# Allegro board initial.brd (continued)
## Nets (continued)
GND: C1.1(A<0>) C2.1(A<0>) C3.1(A<0>) C4.2(B<0>) C5.1(A<0>) C6.1(A<0>) C7.1(A<0>) C8.1(A<0>) C9.1(A<0>) C10.1(A<0>) C11.1(A<0>) C12.1(A<0>) C13.1(A<0>) C14.1(A<0>) C15.1(A<0>) C16.1(A<0>) C17.1(A<0>) C18.1(A<0>) C19.1(A<0>) C20.1(A<0>) C21.1(A<0>) C24.1(A<0>) C25.1(A<0>) C26.1(A<0>) C27.1(A<0>) C28.1(A<0>) C29.1(A<0>) C30.1(A<0>) C31.1(A<0>) C32.1(A<0>) C33.1(A<0>) C34.1(A<0>) C35.1(A<0>) C40.1(A<0>) C41.1(A<0>) C42.1(A<0>) C43.1(A<0>) C44.1(A<0>) C45.1(A<0>) C46.1(A<0>) C47.1(A<0>) C48.1(A<0>) C49.1(A<0>) C50.1(A<0>) C51.1(A<0>) C52.1(A<0>) C53.1(A<0>) C54.1(A<0>) C55.1(A<0>) C56.1(A<0>) C57.1(A<0>) C58.1(A<0>) C61.1(A<0>) C62.1(A<0>) C63.1(A<0>) C64.1(A<0>) C65.1(A<0>) C66.1(A<0>) C67.1(A<0>) C68.1(A<0>) C69.1(A<0>) C70.1(A<0>) C75.1(A<0>) C76.1(A<0>) C77.1(A<0>) C78.1(A<0>) C79.1(A<0>) C80.1(A<0>) C81.1(A<0>) C83.1(A<0>) C84.1(A<0>) C85.1(A<0>) C86.1(A<0>) C87.1(A<0>) C88.1(A<0>) C89.1(A<0>) C90.1(A<0>) C91.1(A<0>) C92.1(A<0>) C93.1(A<0>) C94.1(A<0>) C95.1(A<0>) C96.1(A<0>) C97.1(A<0>) C98.1(A<0>) C99.1(A<0>) C100.1(A<0>) C101.1(A<0>) C106.1(A<0>) C107.1(A<0>) C108.1(A<0>) C109.1(A<0>) C110.1(A<0>) C111.1(A<0>) C112.1(A<0>) C113.1(A<0>) C114.1(A<0>) C115.1(A<0>) C120.1(A<0>) C121.1(A<0>) C122.1(A<0>) C123.1(A<0>) C124.1(A<0>) C125.1(A<0>) C126.1(A<0>) C127.1(A<0>) C128.1(A<0>) C129.1(A<0>) C134.1(A<0>) C135.1(A<0>) C136.1(A<0>) C137.1(A<0>) C138.1(A<0>) C139.1(A<0>) C140.1(A<0>) C141.1(A<0>) C142.1(A<0>) C143.1(A<0>) C148.1(A<0>) C149.1(A<0>) C150.1(A<0>) C151.1(A<0>) C152.1(A<0>) C153.1(A<0>) C154.1(A<0>) C155.1(A<0>) C156.1(A<0>) C157.1(A<0>) C162.1(A<0>) C163.1(A<0>) C164.1(A<0>) C165.1(A<0>) C166.1(A<0>) C167.1(A<0>) C168.1(A<0>) C169.1(A<0>) C170.1(A<0>) C171.1(A<0>) C176.1(A<0>) C177.1(A<0>) C178.1(A<0>) C179.1(A<0>) C180.1(A<0>) C181.1(A<0>) C182.1(A<0>) C183.1(A<0>) C184.1(A<0>) C185.1(A<0>) C186.1(A<0>) C187.1(A<0>) DS2.2(K1) DS3.2(K1) DS4.2(K1) LK5.1(A<0>) LK5.2(B<0>) LK6.1(A<0>) LK6.2(B<0>) LK7.1(A<0>) LK7.2(B<0>) LK8.1(A<0>) LK8.2(B<0>) LK9.1(A<0>) LK10.1(A<0>) PL1.1(A<0>) PL2.1(A<0>) PL3.1(A<0>) PL4.1(A<0>) PL5.1(A<0>) PL6.1(A<0>) PL7.1(A<0>) PL9.AB1(GND1) PL9.AB2(GND2) PL9.AB3(GND3) PL9.AB4(GND4) PL9.AB5(GND5) PL9.AB6(GND6) PL9.AB7(GND7) PL9.AB8(GND8) PL9.AB9(GND9) PL9.AB10(GND10) PL9.CD1(GND11) PL9.CD2(GND12) PL9.CD3(GND13) PL9.CD4(GND14) PL9.CD5(GND15) PL9.CD6(GND16) PL9.CD7(GND17) PL9.CD8(GND18) PL9.CD9(GND19) PL9.CD10(GND20) PL9.EF1(GND21) PL9.EF2(GND22) PL9.EF3(GND23) PL9.EF4(GND24) PL9.EF5(GND25) PL9.EF6(GND26) PL9.EF7(GND27) PL9.EF8(GND28) PL9.EF9(GND29) PL9.EF10(GND30) PL10.AB1(GND1) PL10.AB2(GND2) PL10.AB3(GND3) PL10.AB4(GND4) PL10.AB5(GND5) PL10.AB6(GND6) PL10.AB7(GND7) PL10.AB8(GND8) PL10.AB9(GND9) PL10.AB10(GND10) PL10.CD1(GND11) PL10.CD2(GND12) PL10.CD3(GND13) PL10.CD4(GND14) PL10.CD5(GND15) PL10.CD6(GND16) PL10.CD7(GND17) PL10.CD8(GND18) PL10.CD9(GND19) PL10.CD10(GND20) PL10.EF1(GND21) PL10.EF2(GND22) PL10.EF3(GND23) PL10.EF4(GND24) PL10.EF5(GND25) PL10.EF6(GND26) PL10.EF7(GND27) PL10.EF8(GND28) PL10.EF9(GND29) PL10.EF10(GND30) R1.1(A<0>) R2.1(A<0>) R7.1(A<0>) R9.1(A<0>) R11.1(A<0>) R13.1(A<0>) R15.1(A<0>) R17.1(A<0>) R19.1(A<0>) R28.1(A<0>) R69.1(A<0>) R71.1(A<0>) R73.1(A<0>) R75.1(A<0>) R77.1(A<0>) R79.1(A<0>) R81.1(A<0>) R90.1(A<0>) R91.1(A<0>) R109.1(A<0>) R122.1(A<0>) R124.1(A<0>) R136.1(A<0>) R137.1(A<0>) R144.1(A<0>) R155.1(A<0>) R157.1(A<0>) R159.1(A<0>) R167.1(A<0>) R172.1(A<0>) R188.1(A<0>) R190.1(A<0>) R203.1(A<0>) R208.1(A<0>) R224.1(A<0>) R226.1(A<0>) R239.1(A<0>) R244.1(A<0>) R260.1(A<0>) R262.1(A<0>) R270.1(A<0>) R271.1(A<0>) R272.1(A<0>) R275.1(A<0>) R310.1(A<0>) R312.1(A<0>) R313.1(A<0>) R315.1(A<0>) R317.1(A<0>) R318.1(A<0>) SK2.9(SHIELD1) SK2.10(SHIELD2) SK4.GND1 SK4.GND2 SK4.GND3 SK4.GND4 SK4.GND5 SK4.GND6 SK4.GND7 SK4.GND8 SK4.GND9 SK4.GND10 SK4.GND11 SW1.1(A<0>) SW1.2(A<1>) SW2.B SW2.D TP5.1(TEST<0>) TP19.1(TEST<0>) TP24.1(TEST<0>) U1.3 U2.1(GND) U3.9(GND1) U3.20(GND2) U4.5(GND) U5.4(GND) U5.5(2A) U5.6(2B) U6.5(GND) U7.1(GND) U8.4(GND) U9.1(GND) U10.4(GND) U11.3(GND) U12.1(GND1) U12.4(GND2) U12.6(ENA*) U12.11(ENB*) U12.15(GND3) U12.18(GND4) U12.22(ENC*) U12.27(END*) U12.29(GND5) U12.32(GND6) U13.1(GND) U14.6(GND1) U14.9(OE2) U14.10(GND2) U15.2(GND) U16.6(GND1) U16.8(OE0) U16.10(GND2) U17.1(GND1) U17.4(GND2) U17.6(ENA*) U17.11(ENB*) U17.15(GND3) U17.18(GND4) U17.22(ENC*) U17.27(END*) U17.29(GND5) U17.32(GND6) U18.1(GND) U19.1(GND) U20.1(GND) U21.1(GND) U22.1(GND) U23.1(GND) U24.1(GND) U25.1(GND) U26.1(GND) U27.1(GND) U28.1(GND) U29.1(GND) U30.3(GND) U31.3(GND) U32.8(VSS) U33.A19(EXTVCC) U33.D23(SGND) U33.G1(PGND1) U33.G23(FCB) U33.H7(PGND2) U33.H9(PGND3) U33.H11(PGND4) U33.H13(PGND5) U33.H15(PGND6) U33.H17(PGND7) U33.J1(PGND8) U33.K7(PGND9) U33.K9(PGND10) U33.K11(PGND11) U33.K13(PGND12) U33.K15(PGND13) U33.K17(PGND14) U33.L2(PGND15) U33.L4(PGND16) U33.L6(PGND17) U33.L8(PGND18) U33.L10(PGND19) U33.L12(PGND20) U33.L14(PGND21) U33.L16(PGND22) U33.L18(PGND23) U33.L20(PGND24) U33.L22(PGND25) U33.M2(PGND26) U33.M4(PGND27) U33.M6(PGND28) U33.M8(PGND29) U33.M10(PGND30) U33.M12(PGND31) U33.M14(PGND32) U33.M16(PGND33) U33.M18(PGND34) U33.M20(PGND35) U33.M22(PGND36) U33.N2(PGND37) U33.N4(PGND38) U33.N6(PGND39) U33.N8(PGND40) U33.N10(PGND41) U33.N12(PGND42) U33.N14(PGND43) U33.N16(PGND44) U33.N18(PGND45) U33.N20(PGND46) U33.N22(PGND47) U34.4(GND) U35.4(GND) U36.1(GND) U37.1(GND) U38.1(GND) U39.1(GND) U40.1(GND) U41.1(GND) U42.1(GND) U43.1(GND) U44.1(GND) U45.1(GND) U46.1(GND) U47.1(GND) U48.1(GND) U49.1(GND) U50.1(GND) U51.1(GND) U52.1(GND) U53.1(GND) U54.1(GND) U55.1(GND) U56.1(GND) U57.1(GND) U58.1(GND) U59.1(GND) U59.21(OE/DM2*) U60.1(GND) U60.21(OE/DM2*)
CLK_4_5_FPGA: PL9.E1(PAIR21_A) R31.2(B<0>) TP18.1(TEST<0>)
CLK_4_5_MAIN: R30.2(B<0>) U3.7(ICLK)
CLK_99: R3.2(B<0>) U3.8(FBIN) U10.2(DIN1) U10.3(DIN2)
CLK_99_S: PL9.E2(PAIR22_A) R5.2(B<0>) TP12.1(TEST<0>)
CLK_EC_RTM: TP13.1(TEST<0>) U4.7(ROUT1) U5.2(1B) U8.1(IN) U14.5(INB)
CLK_EC_RTM_N: PL9.B3(PAIR3_B) R273.1(A<0>) U4.1(RIN1*)
CLK_EC_RTM_P: PL9.A3(PAIR3_A) R273.2(B<0>) U4.2(RIN1)
CLK_LA_N: SK4.2LA U12.35(D3Z)
CLK_LA_P: SK4.1LA U12.36(D3Y)
CLK_LB_N: SK4.2LB U12.39(D1Z)
CLK_LB_P: SK4.1LB U12.40(D1Y)
CLK_LC_N: SK4.2LC U12.43(C3Z)
CLK_LC_P: SK4.1LC U12.44(C3Y)
CLK_LD_N: SK4.2LD U12.47(C1Z)
CLK_LD_P: SK4.1LD U12.48(C1Y)
CLK_LE_N: SK4.2LE U12.51(B3Z)
CLK_LE_P: SK4.1LE U12.52(B3Y)
CLK_LF_N: SK4.2LF U12.55(B1Z)
CLK_LF_P: SK4.1LF U12.56(B1Y)
CLK_LG_N: SK4.2LG U12.59(A3Z)
CLK_LG_P: SK4.1LG U12.60(A3Y)
CLK_LH_N: SK4.2LH U12.63(A1Z)
CLK_LH_P: SK4.1LH U12.64(A1Y)
CLK_UA_N: SK4.2UA TP16.1(TEST<0>) U12.33(D4Z)
CLK_UA_P: SK4.1UA TP15.1(TEST<0>) U12.34(D4Y)
CLK_UB_N: SK4.2UB U12.37(D2Z)
CLK_UB_P: SK4.1UB U12.38(D2Y)
CLK_UC_N: SK4.2UC U12.41(C4Z)
CLK_UC_P: SK4.1UC U12.42(C4Y)
CLK_UD_N: SK4.2UD U12.45(C2Z)
CLK_UD_P: SK4.1UD U12.46(C2Y)
CLK_UE_N: SK4.2UE U12.49(B4Z)
CLK_UE_P: SK4.1UE U12.50(B4Y)
CLK_UF_N: SK4.2UF U12.53(B2Z)
CLK_UF_P: SK4.1UF U12.54(B2Y)
CLK_UG_N: SK4.2UG U12.57(A4Z)
CLK_UG_P: SK4.1UG U12.58(A4Y)
CLK_UH_N: SK4.2UH U12.61(A2Z)
CLK_UH_P: SK4.1UH U12.62(A2Y)
DATA_LA_N: SK4.5LA U17.35(D3Z)
DATA_LA_P: SK4.4LA U17.36(D3Y)
DATA_LB_N: SK4.5LB U17.39(D1Z)
DATA_LB_P: SK4.4LB U17.40(D1Y)
DATA_LC_N: SK4.5LC U17.43(C3Z)
DATA_LC_P: SK4.4LC U17.44(C3Y)
DATA_LD_N: SK4.5LD U17.47(C1Z)
DATA_LD_P: SK4.4LD U17.48(C1Y)
DATA_LE_N: SK4.5LE U17.51(B3Z)
DATA_LE_P: SK4.4LE U17.52(B3Y)
DATA_LF_N: SK4.5LF U17.55(B1Z)
DATA_LF_P: SK4.4LF U17.56(B1Y)
DATA_LG_N: SK4.5LG U17.59(A3Z)
DATA_LG_P: SK4.4LG U17.60(A3Y)
DATA_LH_N: SK4.5LH U17.63(A1Z)
DATA_LH_P: SK4.4LH U17.64(A1Y)
DATA_UA_N: SK4.5UA TP22.1(TEST<0>) U17.33(D4Z)
DATA_UA_P: SK4.4UA TP21.1(TEST<0>) U17.34(D4Y)
DATA_UB_N: SK4.5UB U17.37(D2Z)
DATA_UB_P: SK4.4UB U17.38(D2Y)
DATA_UC_N: SK4.5UC U17.41(C4Z)
DATA_UC_P: SK4.4UC U17.42(C4Y)
DATA_UD_N: SK4.5UD U17.45(C2Z)
DATA_UD_P: SK4.4UD U17.46(C2Y)
DATA_UE_N: SK4.5UE U17.49(B4Z)
DATA_UE_P: SK4.4UE U17.50(B4Y)
DATA_UF_N: SK4.5UF U17.53(B2Z)
DATA_UF_P: SK4.4UF U17.54(B2Y)
DATA_UG_N: SK4.5UG U17.57(A4Z)
DATA_UG_P: SK4.4UG U17.58(A4Y)
DATA_UH_N: SK4.5UH U17.61(A2Z)
DATA_UH_P: SK4.4UH U17.62(A2Y)
DIV2: R1.2(B<0>) U3.3(DIV2)
DRIVE_ST: PL1.2(B<0>) U3.11(2XDRIVE)
ENABLE: R140.1(A<0>) U31.2(A) U32.5(P1)
ESD_SEGMENT_1: R274.2(B<0>)
ESD_SEGMENT_2: R275.2(B<0>)
ESD_SEGMENT_3: R274.1(A<0>)
FAILURE_LED: DS1.2(K1) R143.1(A<0>) U32.9(P4)
FAST_CLK_FPGA_N: PL9.D3(PAIR13_B) U13.7(OUT-)
FAST_CLK_FPGA_P: PL9.C3(PAIR13_A) U13.6(OUT+)
FAST_DATA_N: PL10.B3(PAIR3_B) R67.1(A<0>) U17.20(B)
FAST_DATA_P: PL10.A3(PAIR3_A) R67.2(B<0>) U17.19(A)
FPGA_F0: PL10.B7(PAIR7_B) U3.12(F0)
FPGA_F1: PL10.A8(PAIR8_A) U3.13(F1)
FPGA_F2: PL10.B8(PAIR8_B) U3.14(F2)
FPGA_F3: PL10.A9(PAIR9_A) U3.15(F3)
FPGA_F4: PL10.B9(PAIR9_B) U3.16(F4)
FPGA_F5: PL10.A10(PAIR10_A) U3.17(F5)
FPGA_F6: PL10.B10(PAIR10_B) U3.18(F6)
FPGA_R0: PL10.A4(PAIR4_A) U3.24(R0)
FPGA_R1: PL10.B4(PAIR4_B) U3.25(R1)
FPGA_R2: PL10.A5(PAIR5_A) U3.26(R2)
FPGA_R3: PL10.B5(PAIR5_B) U3.27(R3)
FPGA_R4: PL10.A6(PAIR6_A) U3.28(R4)
FPGA_R5: PL10.B6(PAIR6_B) U3.1(R5)
FPGA_R6: PL10.A7(PAIR7_A) U3.2(R6)
FPGA_SPARE_IN1_I_N: C34.2(B<0>) C36.1(A<0>) R82.2(B<0>) SK2.2
FPGA_SPARE_IN1_I_P: C32.2(B<0>) C37.1(A<0>) R82.1(A<0>) SK2.1
FPGA_SPARE_IN1_N: PL10.B2(PAIR2_B) R96.2(B<0>) U18.7(OUT-) U20.2(IN-)
FPGA_SPARE_IN1_P: PL10.A2(PAIR2_A) R96.1(A<0>) U18.6(OUT+) U20.3(IN+)
FPGA_SPARE_IN2_I_N: C35.2(B<0>) C38.1(A<0>) R83.2(B<0>) SK2.5
FPGA_SPARE_IN2_I_P: C33.2(B<0>) C39.1(A<0>) R83.1(A<0>) SK2.4
FPGA_SPARE_IN2_N: PL9.B10(PAIR10_B) R97.2(B<0>) U19.7(OUT-) U21.2(IN-)
FPGA_SPARE_IN2_P: PL9.A10(PAIR10_A) R97.1(A<0>) U19.6(OUT+) U21.3(IN+)
FPGA_SPARE_OUT1_I_N: SK2.8 U22.7(OUT-)
FPGA_SPARE_OUT1_I_P: SK2.7 U22.6(OUT+)
FPGA_SPARE_OUT1_N: PL10.B1(PAIR1_B) R100.1(A<0>) U22.3(IN+)
FPGA_SPARE_OUT1_P: PL10.A1(PAIR1_A) R100.2(B<0>) U22.2(IN-)
FPGA_SPARE_OUT2_I_N: SK2.6 U23.7(OUT-)
FPGA_SPARE_OUT2_I_P: SK2.3 U23.6(OUT+)
FPGA_SPARE_OUT2_N: PL9.B9(PAIR9_B) R101.2(B<0>) U23.2(IN-)
FPGA_SPARE_OUT2_P: PL9.A9(PAIR9_A) R101.1(A<0>) U23.3(IN+)
HSWAP_LED: R146.1(A<0>) U32.11(P6)
I2C_SCL: PL9.D2(PAIR12_B) R150.1(A<0>) TP8.1(TEST<0>) U32.14(SCL) U34.6(SCL) U35.2(SCL)
I2C_SDA: PL9.D1(PAIR11_B) R149.1(A<0>) TP7.1(TEST<0>) U32.15(SDA) U34.5(SDA) U35.1(SDA)
LED_LA_1: SK4.LLLA_K U59.5(OUT0)
LED_LA_2: SK4.LRLA_K U60.5(OUT0)
LED_LB_1: SK4.LLLB_K U59.7(OUT2)
LED_LB_2: SK4.LRLB_K U60.7(OUT2)
LED_LC_1: SK4.LLLC_K U59.9(OUT4)
LED_LC_2: SK4.LRLC_K U60.9(OUT4)
LED_LD_1: SK4.LLLD_K U59.11(OUT6)
LED_LD_2: SK4.LRLD_K U60.11(OUT6)
LED_LE_1: SK4.LLLE_K U59.13(OUT8)
LED_LE_2: SK4.LRLE_K U60.13(OUT8)
LED_LE_A: PL10.D1(PAIR11_B) U59.4(LE/DM1)
LED_LE_B: PL10.F10(PAIR30_B) U60.4(LE/DM1)
LED_LF_1: SK4.LLLF_K U59.15(OUT10)
LED_LF_2: SK4.LRLF_K U60.15(OUT10)
LED_LG_1: SK4.LLLG_K U59.17(OUT12)
LED_LG_2: SK4.LRLG_K U60.17(OUT12)
LED_LH_1: SK4.LLLH_K U59.19(OUT14)
LED_LH_2: SK4.LRLH_K U60.19(OUT14)
LED_SCL: PL10.C2(PAIR12_A) U59.3(CLK) U60.3(CLK)
LED_SDI_A: PL10.C1(PAIR11_A) TP20.1(TEST<0>) U59.2(SDI)
LED_SDI_B: PL10.E10(PAIR30_A) TP23.1(TEST<0>) U60.2(SDI)
LED_UA_1: SK4.ULLA_K U59.6(OUT1)
LED_UA_2: SK4.URLA_K U60.6(OUT1)
LED_UB_1: SK4.ULLB_K U59.8(OUT3)
LED_UB_2: SK4.URLB_K U60.8(OUT3)
LED_UC_1: SK4.ULLC_K U59.10(OUT5)
LED_UC_2: SK4.URLC_K U60.10(OUT5)
LED_UD_1: SK4.ULLD_K U59.12(OUT7)
LED_UD_2: SK4.URLD_K U60.12(OUT7)
LED_UE_1: SK4.ULLE_K U59.14(OUT9)
LED_UE_2: SK4.URLE_K U60.14(OUT9)
LED_UF_1: SK4.ULLF_K U59.16(OUT11)
LED_UF_2: SK4.URLF_K U60.16(OUT11)
LED_UG_1: SK4.ULLG_K U59.18(OUT13)
LED_UG_2: SK4.URLG_K U60.18(OUT13)
LED_UH_1: SK4.ULLH_K U59.20(OUT15)
LED_UH_2: SK4.URLH_K U60.20(OUT15)
NO_4_5_MHZ: PL9.A4(PAIR4_A) U14.11(NO_INB)
NO_9_MHZ: PL9.B4(PAIR4_B) U14.12(NO_INA)
PGOOD: R139.1(A<0>) U1.4(Y) U32.4(P0)
RESET: R141.1(A<0>) U32.6(P2)
RUN_SS_DC: R135.1(A<0>) R136.2(B<0>) U31.4(Y) U33.F23(RUN/SS)
SPARE_PAIR_1N: PL9.B5(PAIR5_B) PL11.2(A2)
SPARE_PAIR_1P: PL9.A5(PAIR5_A) PL11.1(A1)
SPARE_PAIR_2N: PL9.B6(PAIR6_B) PL11.4(A4)
SPARE_PAIR_2P: PL9.A6(PAIR6_A) PL11.3(A3)
SPARE_PAIR_3N: PL9.B7(PAIR7_B) PL11.6(A6)
SPARE_PAIR_3P: PL9.A7(PAIR7_A) PL11.5(A5)
SPARE_PAIR_4N: PL9.B8(PAIR8_B) PL11.8(A8)
SPARE_PAIR_4P: PL9.A8(PAIR8_A) PL11.7(A7)
STATUS_LA_N: C19.2(B<0>) C22.1(A<0>) R20.2(B<0>) SK4.6LA
STATUS_LA_P: C18.2(B<0>) C23.1(A<0>) R20.1(A<0>) SK4.3LA
STATUS_LB_N: C69.2(B<0>) C73.1(A<0>) R114.2(B<0>) SK4.6LB
STATUS_LB_P: C66.2(B<0>) C74.1(A<0>) R114.1(A<0>) SK4.3LB
STATUS_LC_N: C56.2(B<0>) C59.1(A<0>) R104.2(B<0>) SK4.6LC
STATUS_LC_P: C53.2(B<0>) C60.1(A<0>) R104.1(A<0>) SK4.3LC
STATUS_LD_N: C68.2(B<0>) C71.1(A<0>) R113.2(B<0>) SK4.6LD
STATUS_LD_P: C65.2(B<0>) C72.1(A<0>) R113.1(A<0>) SK4.3LD
STATUS_LE_N: C100.2(B<0>) C104.1(A<0>) R162.2(B<0>) SK4.6LE
STATUS_LE_P: C97.2(B<0>) C105.1(A<0>) R162.1(A<0>) SK4.3LE
STATUS_LF_N: C113.2(B<0>) C118.1(A<0>) R180.2(B<0>) SK4.6LF
STATUS_LF_P: C111.2(B<0>) C119.1(A<0>) R180.1(A<0>) SK4.3LF
STATUS_LG_N: C98.2(B<0>) C102.1(A<0>) R161.2(B<0>) SK4.6LG
STATUS_LG_P: C94.2(B<0>) C103.1(A<0>) R161.1(A<0>) SK4.3LG
STATUS_LH_N: C112.2(B<0>) C116.1(A<0>) R179.2(B<0>) SK4.6LH
STATUS_LH_P: C110.2(B<0>) C117.1(A<0>) R179.1(A<0>) SK4.3LH
STATUS_OUT_LA_N: PL10.F1(PAIR21_B) R37.2(B<0>) U7.7(OUT-) U9.2(IN-)
STATUS_OUT_LA_P: PL10.E1(PAIR21_A) R37.1(A<0>) U7.6(OUT+) U9.3(IN+)
STATUS_OUT_LB_N: PL10.F3(PAIR23_B) R128.2(B<0>) U27.7(OUT-) U29.2(IN-)
STATUS_OUT_LB_P: PL10.E3(PAIR23_A) R128.1(A<0>) U27.6(OUT+) U29.3(IN+)
STATUS_OUT_LC_N: PL10.F5(PAIR25_B) R111.2(B<0>) U24.7(OUT-) U25.2(IN-)
STATUS_OUT_LC_P: PL10.E5(PAIR25_A) R111.1(A<0>) U24.6(OUT+) U25.3(IN+)
STATUS_OUT_LD_N: PL10.F7(PAIR27_B) R127.2(B<0>) U26.7(OUT-) U28.2(IN-)
STATUS_OUT_LD_P: PL10.E7(PAIR27_A) R127.1(A<0>) U26.6(OUT+) U28.3(IN+)
STATUS_OUT_LE_N: PL10.F9(PAIR29_B) R176.2(B<0>) U37.7(OUT-) U39.2(IN-)
STATUS_OUT_LE_P: PL10.E9(PAIR29_A) R176.1(A<0>) U37.6(OUT+) U39.3(IN+)
STATUS_OUT_LF_N: PL9.F4(PAIR24_B) R194.2(B<0>) U41.7(OUT-) U43.2(IN-)
STATUS_OUT_LF_P: PL9.E4(PAIR24_A) R194.1(A<0>) U41.6(OUT+) U43.3(IN+)
STATUS_OUT_LG_N: PL9.F6(PAIR26_B) R175.2(B<0>) U36.7(OUT-) U38.2(IN-)
STATUS_OUT_LG_P: PL9.E6(PAIR26_A) R175.1(A<0>) U36.6(OUT+) U38.3(IN+)
STATUS_OUT_LH_N: PL9.F8(PAIR28_B) R193.2(B<0>) U40.7(OUT-) U42.2(IN-)
STATUS_OUT_LH_P: PL9.E8(PAIR28_A) R193.1(A<0>) U40.6(OUT+) U42.3(IN+)
STATUS_OUT_UA_N: PL10.F2(PAIR22_B) R248.2(B<0>) U2.7(OUT-) U54.2(IN-)
STATUS_OUT_UA_P: PL10.E2(PAIR22_A) R248.1(A<0>) U2.6(OUT+) U54.3(IN+)
STATUS_OUT_UB_N: PL10.F4(PAIR24_B) R266.2(B<0>) U56.7(OUT-) U58.2(IN-)
STATUS_OUT_UB_P: PL10.E4(PAIR24_A) R266.1(A<0>) U56.6(OUT+) U58.3(IN+)
STATUS_OUT_UC_N: PL10.F6(PAIR26_B) R247.2(B<0>) U52.7(OUT-) U53.2(IN-)
STATUS_OUT_UC_P: PL10.E6(PAIR26_A) R247.1(A<0>) U52.6(OUT+) U53.3(IN+)
STATUS_OUT_UD_N: PL10.F8(PAIR28_B) R265.2(B<0>) U55.7(OUT-) U57.2(IN-)
STATUS_OUT_UD_P: PL10.E8(PAIR28_A) R265.1(A<0>) U55.6(OUT+) U57.3(IN+)
STATUS_OUT_UE_N: PL9.F3(PAIR23_B) R212.2(B<0>) U45.7(OUT-) U47.2(IN-)
STATUS_OUT_UE_P: PL9.E3(PAIR23_A) R212.1(A<0>) U45.6(OUT+) U47.3(IN+)
STATUS_OUT_UF_N: PL9.F5(PAIR25_B) R230.2(B<0>) U49.7(OUT-) U51.2(IN-)
STATUS_OUT_UF_P: PL9.E5(PAIR25_A) R230.1(A<0>) U49.6(OUT+) U51.3(IN+)
STATUS_OUT_UG_N: PL9.F7(PAIR27_B) R211.2(B<0>) U44.7(OUT-) U46.2(IN-)
STATUS_OUT_UG_P: PL9.E7(PAIR27_A) R211.1(A<0>) U44.6(OUT+) U46.3(IN+)
STATUS_OUT_UH_N: PL9.F9(PAIR29_B) R229.2(B<0>) TP4.1(TEST<0>) U48.7(OUT-) U50.2(IN-)
STATUS_OUT_UH_P: PL9.E9(PAIR29_A) R229.1(A<0>) TP3.1(TEST<0>) U48.6(OUT+) U50.3(IN+)
STATUS_UA_N: C155.2(B<0>) C160.1(A<0>) R234.2(B<0>) SK4.6UA
STATUS_UA_P: C153.2(B<0>) C161.1(A<0>) R234.1(A<0>) SK4.3UA
STATUS_UB_N: C169.2(B<0>) C174.1(A<0>) R252.2(B<0>) SK4.6UB
STATUS_UB_P: C167.2(B<0>) C175.1(A<0>) R252.1(A<0>) SK4.3UB
STATUS_UC_N: C154.2(B<0>) C158.1(A<0>) R233.2(B<0>) SK4.6UC
STATUS_UC_P: C150.2(B<0>) C159.1(A<0>) R233.1(A<0>) SK4.3UC
STATUS_UD_N: C168.2(B<0>) C172.1(A<0>) R251.2(B<0>) SK4.6UD
STATUS_UD_P: C165.2(B<0>) C173.1(A<0>) R251.1(A<0>) SK4.3UD
STATUS_UE_N: C127.2(B<0>) C132.1(A<0>) R198.2(B<0>) SK4.6UE
STATUS_UE_P: C125.2(B<0>) C133.1(A<0>) R198.1(A<0>) SK4.3UE
STATUS_UF_N: C141.2(B<0>) C146.1(A<0>) R216.2(B<0>) SK4.6UF
STATUS_UF_P: C139.2(B<0>) C147.1(A<0>) R216.1(A<0>) SK4.3UF
STATUS_UG_N: C126.2(B<0>) C130.1(A<0>) R197.2(B<0>) SK4.6UG
STATUS_UG_P: C122.2(B<0>) C131.1(A<0>) R197.1(A<0>) SK4.3UG
STATUS_UH_N: C140.2(B<0>) C144.1(A<0>) R215.2(B<0>) SK4.6UH TP1.1(TEST<0>)
STATUS_UH_P: C137.2(B<0>) C145.1(A<0>) R215.1(A<0>) SK4.3UH TP2.1(TEST<0>)
SW_HOT_SWAP: DS5.2(K1) R142.1(A<0>) SW2.A SW2.C U32.7(P3)
UNNAMED_1_CAPACITOR_I90_B: C36.2(B<0>) R84.1(A<0>) R85.2(B<0>) R92.1(A<0>) U18.2(IN-)
UNNAMED_1_CAPACITOR_I99_B: C37.2(B<0>) R85.1(A<0>) R86.2(B<0>) R90.2(B<0>) U18.3(IN+)
UNNAMED_1_CAPACITOR_I100_B: C38.2(B<0>) R87.1(A<0>) R88.2(B<0>) R93.1(A<0>) U19.2(IN-)
UNNAMED_1_CAPACITOR_I101_B: C39.2(B<0>) R88.1(A<0>) R89.2(B<0>) R91.2(B<0>) U19.3(IN+)
UNNAMED_1_DS90LV001_I70_EN: R102.1(A<0>) U22.8(EN)
UNNAMED_1_DS90LV001_I71_EN: R103.1(A<0>) U23.8(EN)
UNNAMED_1_DS90LV001_I78_EN: R94.1(A<0>) U18.8(EN)
UNNAMED_1_DS90LV001_I79_EN: R98.1(A<0>) U20.8(EN)
UNNAMED_1_DS90LV001_I79_OUT: R86.1(A<0>) U20.6(OUT+)
UNNAMED_1_DS90LV001_I79_OUT_1: R84.2(B<0>) U20.7(OUT-)
UNNAMED_1_DS90LV001_I80_EN: R99.1(A<0>) U21.8(EN)
UNNAMED_1_DS90LV001_I80_OUT: R89.1(A<0>) U21.6(OUT+)
UNNAMED_1_DS90LV001_I80_OUT_1: R87.2(B<0>) U21.7(OUT-)
UNNAMED_1_DS90LV001_I81_EN: R95.1(A<0>) U19.8(EN)
UNNAMED_2_CAPACITOR_I8_B: C22.2(B<0>) R24.1(A<0>) R25.2(B<0>) R27.1(A<0>) U7.2(IN-)
UNNAMED_2_CAPACITOR_I25_B: C23.2(B<0>) R25.1(A<0>) R26.2(B<0>) R28.2(B<0>) U7.3(IN+)
UNNAMED_2_CAPACITOR_I157_B: C73.2(B<0>) R118.1(A<0>) R119.2(B<0>) R123.1(A<0>) U27.2(IN-)
UNNAMED_2_CAPACITOR_I170_B: C74.2(B<0>) R119.1(A<0>) R120.2(B<0>) R124.2(B<0>) U27.3(IN+)
UNNAMED_2_CAPACITOR_I189_B: C59.2(B<0>) R105.1(A<0>) R106.2(B<0>) R108.1(A<0>) U24.2(IN-)
UNNAMED_2_CAPACITOR_I190_B: C60.2(B<0>) R106.1(A<0>) R107.2(B<0>) R109.2(B<0>) U24.3(IN+)
UNNAMED_2_CAPACITOR_I209_B: C71.2(B<0>) R115.1(A<0>) R116.2(B<0>) R121.1(A<0>) U26.2(IN-)
UNNAMED_2_CAPACITOR_I210_B: C72.2(B<0>) R116.1(A<0>) R117.2(B<0>) R122.2(B<0>) U26.3(IN+)
UNNAMED_2_DS90LV001_I18_EN: R35.1(A<0>) U7.8(EN)
UNNAMED_2_DS90LV001_I19_EN: R39.1(A<0>) U9.8(EN)
UNNAMED_2_DS90LV001_I19_OUT: R24.2(B<0>) U9.7(OUT-)
UNNAMED_2_DS90LV001_I19_OUT_1: R26.1(A<0>) U9.6(OUT+)
UNNAMED_2_DS90LV001_I162_EN: R130.1(A<0>) U29.8(EN)
UNNAMED_2_DS90LV001_I162_OUT: R118.2(B<0>) U29.7(OUT-)
UNNAMED_2_DS90LV001_I162_OUT_1: R120.1(A<0>) U29.6(OUT+)
UNNAMED_2_DS90LV001_I166_EN: R126.1(A<0>) U27.8(EN)
UNNAMED_2_DS90LV001_I181_EN: R112.1(A<0>) U25.8(EN)
UNNAMED_2_DS90LV001_I181_OUT: R107.1(A<0>) U25.6(OUT+)
UNNAMED_2_DS90LV001_I181_OUT_1: R105.2(B<0>) U25.7(OUT-)
UNNAMED_2_DS90LV001_I185_EN: R110.1(A<0>) U24.8(EN)
UNNAMED_2_DS90LV001_I201_EN: R129.1(A<0>) U28.8(EN)
UNNAMED_2_DS90LV001_I201_OUT: R115.2(B<0>) U28.7(OUT-)
UNNAMED_2_DS90LV001_I201_OUT_1: R117.1(A<0>) U28.6(OUT+)
UNNAMED_2_DS90LV001_I205_EN: R125.1(A<0>) U26.8(EN)
UNNAMED_4_CAPACITOR_I14_B: C159.2(B<0>) R236.1(A<0>) R237.2(B<0>) R239.2(B<0>) U52.3(IN+)
UNNAMED_4_CAPACITOR_I15_B: C158.2(B<0>) R235.1(A<0>) R236.2(B<0>) R238.1(A<0>) U52.2(IN-)
UNNAMED_4_CAPACITOR_I30_B: C161.2(B<0>) R241.1(A<0>) R242.2(B<0>) R244.2(B<0>) U2.3(IN+)
UNNAMED_4_CAPACITOR_I31_B: C160.2(B<0>) R240.1(A<0>) R241.2(B<0>) R243.1(A<0>) U2.2(IN-)
UNNAMED_4_CAPACITOR_I61_B: C173.2(B<0>) R254.1(A<0>) R255.2(B<0>) R260.2(B<0>) U55.3(IN+)
UNNAMED_4_CAPACITOR_I62_B: C172.2(B<0>) R253.1(A<0>) R254.2(B<0>) R259.1(A<0>) U55.2(IN-)
UNNAMED_4_CAPACITOR_I79_B: C175.2(B<0>) R257.1(A<0>) R258.2(B<0>) R262.2(B<0>) U56.3(IN+)
UNNAMED_4_CAPACITOR_I80_B: C174.2(B<0>) R256.1(A<0>) R257.2(B<0>) R261.1(A<0>) U56.2(IN-)
UNNAMED_4_DS90LV001_I18_EN: R245.1(A<0>) U52.8(EN)
UNNAMED_4_DS90LV001_I38_EN: R249.1(A<0>) U53.8(EN)
UNNAMED_4_DS90LV001_I38_OUT: R235.2(B<0>) U53.7(OUT-)
UNNAMED_4_DS90LV001_I38_OUT_1: R237.1(A<0>) U53.6(OUT+)
UNNAMED_4_DS90LV001_I39_EN: R246.1(A<0>) U2.8(EN)
UNNAMED_4_DS90LV001_I43_EN: R250.1(A<0>) U54.8(EN)
UNNAMED_4_DS90LV001_I43_OUT: R242.1(A<0>) U54.6(OUT+)
UNNAMED_4_DS90LV001_I43_OUT_1: R240.2(B<0>) U54.7(OUT-)
UNNAMED_4_DS90LV001_I68_EN: R263.1(A<0>) U55.8(EN)
UNNAMED_4_DS90LV001_I85_EN: R264.1(A<0>) U56.8(EN)
UNNAMED_4_DS90LV001_I90_EN: R267.1(A<0>) U57.8(EN)
UNNAMED_4_DS90LV001_I90_OUT: R253.2(B<0>) U57.7(OUT-)
UNNAMED_4_DS90LV001_I90_OUT_1: R255.1(A<0>) U57.6(OUT+)
UNNAMED_4_DS90LV001_I94_EN: R268.1(A<0>) U58.8(EN)
UNNAMED_4_DS90LV001_I94_OUT: R256.2(B<0>) U58.7(OUT-)
UNNAMED_4_DS90LV001_I94_OUT_1: R258.1(A<0>) U58.6(OUT+)
UNNAMED_5_CAPACITOR_I14_B: C131.2(B<0>) R200.1(A<0>) R201.2(B<0>) R203.2(B<0>) U44.3(IN+)
UNNAMED_5_CAPACITOR_I15_B: C130.2(B<0>) R199.1(A<0>) R200.2(B<0>) R202.1(A<0>) U44.2(IN-)
UNNAMED_5_CAPACITOR_I30_B: C133.2(B<0>) R205.1(A<0>) R206.2(B<0>) R208.2(B<0>) U45.3(IN+)
UNNAMED_5_CAPACITOR_I31_B: C132.2(B<0>) R204.1(A<0>) R205.2(B<0>) R207.1(A<0>) U45.2(IN-)
UNNAMED_5_CAPACITOR_I61_B: C145.2(B<0>) R218.1(A<0>) R219.2(B<0>) R224.2(B<0>) U48.3(IN+)
UNNAMED_5_CAPACITOR_I62_B: C144.2(B<0>) R217.1(A<0>) R218.2(B<0>) R223.1(A<0>) U48.2(IN-)
UNNAMED_5_CAPACITOR_I79_B: C147.2(B<0>) R221.1(A<0>) R222.2(B<0>) R226.2(B<0>) U49.3(IN+)
UNNAMED_5_CAPACITOR_I80_B: C146.2(B<0>) R220.1(A<0>) R221.2(B<0>) R225.1(A<0>) U49.2(IN-)
UNNAMED_5_DS90LV001_I18_EN: R209.1(A<0>) U44.8(EN)
UNNAMED_5_DS90LV001_I38_EN: R213.1(A<0>) U46.8(EN)
UNNAMED_5_DS90LV001_I38_OUT: R201.1(A<0>) U46.6(OUT+)
UNNAMED_5_DS90LV001_I38_OUT_1: R199.2(B<0>) U46.7(OUT-)
UNNAMED_5_DS90LV001_I39_EN: R210.1(A<0>) U45.8(EN)
UNNAMED_5_DS90LV001_I43_EN: R214.1(A<0>) U47.8(EN)
UNNAMED_5_DS90LV001_I43_OUT: R206.1(A<0>) U47.6(OUT+)
UNNAMED_5_DS90LV001_I43_OUT_1: R204.2(B<0>) U47.7(OUT-)
UNNAMED_5_DS90LV001_I68_EN: R227.1(A<0>) U48.8(EN)
UNNAMED_5_DS90LV001_I85_EN: R228.1(A<0>) U49.8(EN)
UNNAMED_5_DS90LV001_I90_EN: R231.1(A<0>) U50.8(EN)
UNNAMED_5_DS90LV001_I90_OUT: R219.1(A<0>) U50.6(OUT+)
UNNAMED_5_DS90LV001_I90_OUT_1: R217.2(B<0>) U50.7(OUT-)
UNNAMED_5_DS90LV001_I94_EN: R232.1(A<0>) U51.8(EN)
UNNAMED_5_DS90LV001_I94_OUT: R222.1(A<0>) U51.6(OUT+)
UNNAMED_5_DS90LV001_I94_OUT_1: R220.2(B<0>) U51.7(OUT-)
UNNAMED_6_74LVC1G34_I76_Y: R134.1(A<0>) U1.2(A) U30.4(Y)
UNNAMED_6_AT24C32C_I14_A0: R314.1(A<0>) R315.2(B<0>) U34.1(A0)
UNNAMED_6_AT24C32C_I14_A1: R316.1(A<0>) R317.2(B<0>) U34.2(A1)
UNNAMED_6_AT24C32C_I14_A2: R148.1(A<0>) R318.2(B<0>) U34.3(A2)
UNNAMED_6_CAPACITOR_I59_B: C81.2(B<0>) R137.2(B<0>) U33.A15(FADJ)
UNNAMED_6_CAPACITOR_I62_A: C82.1(A<0>) R144.2(B<0>) U33.A21(VOSET)
UNNAMED_6_LED-SMD_I19_A1: DS5.1(A1) R151.2(B<0>)
UNNAMED_6_LED-SMD_I21_A1: DS6.1(A1) R152.2(B<0>)
UNNAMED_6_LED-SMD_I22_A1: DS1.1(A1) R153.2(B<0>)
UNNAMED_6_LED-SMD_I70_A1: DS3.1(A1) R132.2(B<0>)
UNNAMED_6_LED-SMD_I71_A1: DS2.1(A1) R131.2(B<0>)
UNNAMED_6_LED-SMD_I81_A1: DS4.1(A1) R134.2(B<0>)
UNNAMED_6_LM75A_I38_A0: R158.1(A<0>) R159.2(B<0>) U35.7(A0)
UNNAMED_6_LM75A_I38_A1: R156.1(A<0>) R157.2(B<0>) U35.6(A1)
UNNAMED_6_LM75A_I38_A2: R154.1(A<0>) R155.2(B<0>) U35.5(A2)
UNNAMED_6_LM75A_I38_OS: R160.1(A<0>) U35.3(OS)
UNNAMED_6_PCF8574_I3_A0: R138.1(A<0>) R313.2(B<0>) U32.1(A0)
UNNAMED_6_PCF8574_I3_A1: R311.1(A<0>) R312.2(B<0>) U32.2(A1)
UNNAMED_6_PCF8574_I3_A2: R309.1(A<0>) R310.2(B<0>) U32.3(A2)
UNNAMED_6_RESISTOR_I107_B: PL9.C1(PAIR11_A) R270.2(B<0>)
UNNAMED_7_2WAY-SPST_I62_B: SW1.3(B<1>) U14.1(SELB)
UNNAMED_7_2WAY-SPST_I62_B_1: SW1.4(B<0>) U14.16(OE1)
UNNAMED_7_3D3225_I154_OUT5: U5.1(1A) U8.5(OUT5)
UNNAMED_7_65LVDS116_I76_A: R21.2(B<0>) R269.2(B<0>) U10.7(DOUT1) U12.19(A) U13.2(IN-)
UNNAMED_7_65LVDS116_I76_B: R21.1(A<0>) R269.1(A<0>) U10.8(DOUT1*) U12.20(B) U13.3(IN+)
UNNAMED_7_65LVDS116_I76_ENA: R12.1(A<0>) R13.2(B<0>) U12.5(ENA)
UNNAMED_7_65LVDS116_I76_ENB: R10.1(A<0>) R11.2(B<0>) U12.10(ENB)
UNNAMED_7_65LVDS116_I76_ENC: R8.1(A<0>) R9.2(B<0>) U12.23(ENC)
UNNAMED_7_65LVDS116_I76_END: R6.1(A<0>) R7.2(B<0>) U12.28(END)
UNNAMED_7_65LVDS116_I76_S0: R18.1(A<0>) R19.2(B<0>) U12.24(S0)
UNNAMED_7_65LVDS116_I76_S1: R16.1(A<0>) R17.2(B<0>) U12.25(S1)
UNNAMED_7_65LVDS116_I76_SM: R14.1(A<0>) R15.2(B<0>) U12.26(SM)
UNNAMED_7_74LVC1G06_I51_A: U5.7(1Y) U11.2(A)
UNNAMED_7_74LVC1G06_I51_Y: TP14.1(TEST<0>) U11.4(Y) U14.4(INA)
UNNAMED_7_DS90LV001_I121_EN: R23.1(A<0>) U13.8(EN)
UNNAMED_7_DS90LV018A_I104_RIN1: R4.2(B<0>) TP11.1(TEST<0>) U6.2(RIN1) U10.6(DOUT2)
UNNAMED_7_DS90LV018A_I104_RIN1_: R4.1(A<0>) TP10.1(TEST<0>) U6.1(RIN1*) U10.5(DOUT2*)
UNNAMED_7_DS90LV018A_I104_ROUT1: R5.1(A<0>) U6.7(ROUT1)
UNNAMED_7_HEADER2X1_I125_B: PL2.2(B<0>) U3.4(S0)
UNNAMED_7_HEADER2X1_I126_B: PL3.2(B<0>) U3.5(S1)
UNNAMED_7_HEADER2X1_I127_B: PL4.2(B<0>) U3.19(PDTS*)
UNNAMED_7_HEADER2X1_I149_B: PL6.2(B<0>) U16.1(S0)
UNNAMED_7_HEADER2X1_I150_B: PL7.2(B<0>) U16.2(S1)
UNNAMED_7_HEADER2X1_I151_B: PL5.2(B<0>) U16.16(DIV)
UNNAMED_7_ICS527-01_I67_CLK1: R3.1(A<0>) U3.22(CLK1)
UNNAMED_7_ICS527-01_I67_OECLK2: R2.2(B<0>) U3.10(OECLK2)
UNNAMED_7_ICS580-01_I60_CLK1: TP17.1(TEST<0>) U14.14(CLK1) U16.4(INA)
UNNAMED_7_ICS581-02_I30_CLK2: R30.1(A<0>) U16.13(CLK2)
UNNAMED_7_ICS581-02_I30_CLK3: R31.1(A<0>) U16.12(CLK3)
UNNAMED_7_ICS581-02_I30_CLK4: U16.7(FBIN) U16.11(CLK4)
UNNAMED_7_ICS581-02_I30_INB: U15.3(OUT<0>) U16.5(INB)
UNNAMED_7_ICS581-02_I30_OE1: R29.1(A<0>) U16.9(OE1)
UNNAMED_7_OSC-SMD_I36_EN: R22.1(A<0>) U15.1(EN<0>)
UNNAMED_8_65LVDS116_I16_ENA: R70.1(A<0>) R71.2(B<0>) U17.5(ENA)
UNNAMED_8_65LVDS116_I16_ENB: R68.1(A<0>) R69.2(B<0>) U17.10(ENB)
UNNAMED_8_65LVDS116_I16_ENC: R80.1(A<0>) R81.2(B<0>) U17.23(ENC)
UNNAMED_8_65LVDS116_I16_END: R78.1(A<0>) R79.2(B<0>) U17.28(END)
UNNAMED_8_65LVDS116_I16_S0: R76.1(A<0>) R77.2(B<0>) U17.24(S0)
UNNAMED_8_65LVDS116_I16_S1: R74.1(A<0>) R75.2(B<0>) U17.25(S1)
UNNAMED_8_65LVDS116_I16_SM: R72.1(A<0>) R73.2(B<0>) U17.26(SM)
UNNAMED_8_RESISTOR_I44_B: R33.2(B<0>) SK4.LRLA_A
UNNAMED_8_RESISTOR_I45_B: R34.2(B<0>) SK4.LLLB_A
UNNAMED_8_RESISTOR_I46_B: R36.2(B<0>) SK4.LRLB_A
UNNAMED_8_RESISTOR_I47_B: R38.2(B<0>) SK4.LLLC_A
UNNAMED_8_RESISTOR_I48_B: R40.2(B<0>) SK4.LRLC_A
UNNAMED_8_RESISTOR_I49_B: R41.2(B<0>) SK4.LLLD_A
UNNAMED_8_RESISTOR_I50_B: R42.2(B<0>) SK4.LRLD_A
UNNAMED_8_RESISTOR_I51_B: R43.2(B<0>) SK4.LLLE_A
UNNAMED_8_RESISTOR_I52_B: R44.2(B<0>) SK4.LRLE_A
UNNAMED_8_RESISTOR_I53_B: R45.2(B<0>) SK4.LLLF_A
UNNAMED_8_RESISTOR_I54_B: R46.2(B<0>) SK4.LRLF_A
UNNAMED_8_RESISTOR_I55_B: R47.2(B<0>) SK4.LLLG_A
UNNAMED_8_RESISTOR_I56_B: R48.2(B<0>) SK4.LRLG_A
UNNAMED_8_RESISTOR_I57_B: R49.2(B<0>) SK4.LLLH_A
UNNAMED_8_RESISTOR_I58_B: R50.2(B<0>) SK4.LRLH_A
UNNAMED_8_RESISTOR_I59_B: R32.2(B<0>) SK4.LLLA_A
UNNAMED_8_RESISTOR_I60_A: R51.1(A<0>) SK4.ULLA_A
UNNAMED_8_RESISTOR_I61_A: R52.1(A<0>) SK4.URLA_A
UNNAMED_8_RESISTOR_I62_A: R53.1(A<0>) SK4.ULLB_A
UNNAMED_8_RESISTOR_I63_A: R54.1(A<0>) SK4.URLB_A
UNNAMED_8_RESISTOR_I64_A: R55.1(A<0>) SK4.ULLC_A
UNNAMED_8_RESISTOR_I65_A: R56.1(A<0>) SK4.URLC_A
UNNAMED_8_RESISTOR_I66_A: R57.1(A<0>) SK4.ULLD_A
UNNAMED_8_RESISTOR_I67_A: R58.1(A<0>) SK4.URLD_A
UNNAMED_8_RESISTOR_I68_A: R59.1(A<0>) SK4.ULLE_A
UNNAMED_8_RESISTOR_I69_A: R60.1(A<0>) SK4.URLE_A
UNNAMED_8_RESISTOR_I70_A: R61.1(A<0>) SK4.ULLF_A
UNNAMED_8_RESISTOR_I71_A: R64.1(A<0>) SK4.URLG_A
UNNAMED_8_RESISTOR_I72_A: R65.1(A<0>) SK4.ULLH_A
UNNAMED_8_RESISTOR_I73_A: R66.1(A<0>) SK4.URLH_A
UNNAMED_8_RESISTOR_I74_A: R62.1(A<0>) SK4.URLF_A
UNNAMED_8_RESISTOR_I75_A: R63.1(A<0>) SK4.ULLG_A
UNNAMED_8_RESISTOR_I135_B: R271.2(B<0>) U59.23(REXT)
UNNAMED_8_RESISTOR_I136_B: R272.2(B<0>) U60.23(REXT)
UNNAMED_10_CAPACITOR_I14_B: C103.2(B<0>) R164.1(A<0>) R165.2(B<0>) R167.2(B<0>) U36.3(IN+)
UNNAMED_10_CAPACITOR_I15_B: C102.2(B<0>) R163.1(A<0>) R164.2(B<0>) R166.1(A<0>) U36.2(IN-)
UNNAMED_10_CAPACITOR_I30_B: C105.2(B<0>) R169.1(A<0>) R170.2(B<0>) R172.2(B<0>) U37.3(IN+)
UNNAMED_10_CAPACITOR_I31_B: C104.2(B<0>) R168.1(A<0>) R169.2(B<0>) R171.1(A<0>) U37.2(IN-)
UNNAMED_10_CAPACITOR_I61_B: C117.2(B<0>) R182.1(A<0>) R183.2(B<0>) R188.2(B<0>) U40.3(IN+)
UNNAMED_10_CAPACITOR_I62_B: C116.2(B<0>) R181.1(A<0>) R182.2(B<0>) R187.1(A<0>) U40.2(IN-)
UNNAMED_10_CAPACITOR_I79_B: C119.2(B<0>) R185.1(A<0>) R186.2(B<0>) R190.2(B<0>) U41.3(IN+)
UNNAMED_10_CAPACITOR_I80_B: C118.2(B<0>) R184.1(A<0>) R185.2(B<0>) R189.1(A<0>) U41.2(IN-)
UNNAMED_10_DS90LV001_I18_EN: R173.1(A<0>) U36.8(EN)
UNNAMED_10_DS90LV001_I38_EN: R177.1(A<0>) U38.8(EN)
UNNAMED_10_DS90LV001_I38_OUT: R165.1(A<0>) U38.6(OUT+)
UNNAMED_10_DS90LV001_I38_OUT_1: R163.2(B<0>) U38.7(OUT-)
UNNAMED_10_DS90LV001_I39_EN: R174.1(A<0>) U37.8(EN)
UNNAMED_10_DS90LV001_I43_EN: R178.1(A<0>) U39.8(EN)
UNNAMED_10_DS90LV001_I43_OUT: R170.1(A<0>) U39.6(OUT+)
UNNAMED_10_DS90LV001_I43_OUT_1: R168.2(B<0>) U39.7(OUT-)
UNNAMED_10_DS90LV001_I68_EN: R191.1(A<0>) U40.8(EN)
UNNAMED_10_DS90LV001_I85_EN: R192.1(A<0>) U41.8(EN)
UNNAMED_10_DS90LV001_I90_EN: R195.1(A<0>) U42.8(EN)
UNNAMED_10_DS90LV001_I90_OUT: R183.1(A<0>) U42.6(OUT+)
UNNAMED_10_DS90LV001_I90_OUT_1: R181.2(B<0>) U42.7(OUT-)
UNNAMED_10_DS90LV001_I94_EN: R196.1(A<0>) U43.8(EN)
UNNAMED_10_DS90LV001_I94_OUT: R186.1(A<0>) U43.6(OUT+)
UNNAMED_10_DS90LV001_I94_OUT_1: R184.2(B<0>) U43.7(OUT-)
USD_LED: DS6.2(K1) R145.1(A<0>) U32.10(P5)
VETO_LA_N: PL10.D3(PAIR13_B) SK4.8LA
VETO_LA_P: PL10.C3(PAIR13_A) SK4.7LA
VETO_LB_N: PL10.D5(PAIR15_B) SK4.8LB
VETO_LB_P: PL10.C5(PAIR15_A) SK4.7LB
VETO_LC_N: PL10.D7(PAIR17_B) SK4.8LC
VETO_LC_P: PL10.C7(PAIR17_A) SK4.7LC
VETO_LD_N: PL10.D9(PAIR19_B) SK4.8LD
VETO_LD_P: PL10.C9(PAIR19_A) SK4.7LD
VETO_LE_N: PL9.D4(PAIR14_B) SK4.8LE
VETO_LE_P: PL9.C4(PAIR14_A) SK4.7LE
VETO_LF_N: PL9.D6(PAIR16_B) SK4.8LF
VETO_LF_P: PL9.C6(PAIR16_A) SK4.7LF
VETO_LG_N: PL9.D8(PAIR18_B) SK4.8LG
VETO_LG_P: PL9.C8(PAIR18_A) SK4.7LG
VETO_LH_N: PL9.D10(PAIR20_B) SK4.8LH
VETO_LH_P: PL9.C10(PAIR20_A) SK4.7LH
VETO_UA_N: PL10.D4(PAIR14_B) SK4.8UA
VETO_UA_P: PL10.C4(PAIR14_A) SK4.7UA
VETO_UB_N: PL10.D6(PAIR16_B) SK4.8UB
VETO_UB_P: PL10.C6(PAIR16_A) SK4.7UB
VETO_UC_N: PL10.D8(PAIR18_B) SK4.8UC
VETO_UC_P: PL10.C8(PAIR18_A) SK4.7UC
VETO_UD_N: PL10.D10(PAIR20_B) SK4.8UD
VETO_UD_P: PL10.C10(PAIR20_A) SK4.7UD
VETO_UE_N: PL9.D5(PAIR15_B) SK4.8UE
VETO_UE_P: PL9.C5(PAIR15_A) SK4.7UE
VETO_UF_N: PL9.D7(PAIR17_B) SK4.8UF
VETO_UF_P: PL9.C7(PAIR17_A) SK4.7UF
VETO_UG_N: PL9.D9(PAIR19_B) SK4.8UG
VETO_UG_P: PL9.C9(PAIR19_A) SK4.7UG
VETO_UH_N: PL9.F10(PAIR30_B) SK4.8UH
VETO_UH_P: PL9.E10(PAIR30_A) SK4.7UH
WP: R147.1(A<0>) U32.12(P7) U34.7(WP)

Pads without a net: PL8 A B C; PL9 F1 F2; PL10 D2; U1 1; U2 4; U3 21; U4 3 4 6; U5 3; U6 3 4 6; U7 4; U8 2 3 6 7; U9 4; U11 1; U12 7 8 9 12 13 14 21; U13 4; U14 2 7 8 13; U16 14; U17 7 8 9 12 13 14 21; U18 4; U19 4; U20 4; U21 4; U22 4; U23 4; U24 4; U25 4; U26 4; U27 4; U28 4; U29 4; U30 1; U31 1; U32 13; U33 A17 B23; U36 4; U37 4; U38 4; U39 4; U40 4; U41 4; U42 4; U43 4; U44 4; U45 4; U46 4; U47 4; U48 4; U49 4; U50 4; U51 4; U52 4; U53 4; U54 4; U55 4; U56 4; U57 4; U58 4; U59 22; U60 22; UXX 1 2 3 4 5 6 7 8 9 10 11 12 13 14 15 16; UXX#2 1 2 3 4 5 6 7 8 9 10 11 12 13 14 15 16

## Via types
v1: diameter 0.66, hole 0.305, TOP to BOTTOM, 795 vias
v2: diameter 0.5, hole 0.3, TOP to BOTTOM, 42 vias

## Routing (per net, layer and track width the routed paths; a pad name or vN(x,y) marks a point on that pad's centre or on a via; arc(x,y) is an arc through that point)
3V3: length 349.5
  TOP w0.15: v1(49,78.05) 48.7,78.35 48.2,78.35 48.1,78.45 R16.2 ; v1(48.6,65.75) 48.3,66.05 47.8,66.05 47.7,66.15 47.66,66.15 ; U12.16 42.05,71.6 41.8,71.35 v1(41.7,71.35) ; U33.T4 v1(131.24,30.83) ; v1(41.7,72.35) 41.8,72.35 42.05,72.1 U12.17 ; U33.P6 133.91,30.2 v2(133.91,30.2) ; U33.R2 v1(133.28,32.88) ; v2(132.64,30.2) 132.65,30.2 U33.R6 ; U33.T6 v1(131.24,29.56) ; U33.P12 133.91,26.39 v2(133.91,26.39) ; v1(41.7,64.35) 41.8,64.35 42.05,64.6 U12.2 ; v1(49,102.05) 48.7,102.35 48.2,102.35 48.1,102.45 R74.2 ; U33.T8 v1(131.24,28.29) ; U16.15 106.74,80.72 106.71,80.69 106.67,80.69 106.06,80.09 C24.2 ; v1(49,99.65) R80.2 R76.2 ; C25.2 115.04,81.38 U16.3 ; C2.2 99.59,76.6 U3.6 ; U33.T10 v1(131.24,27.02) ; v1(41.8,103.35) 41.9,103.35 42.15,103.1 U17.31 ; v1(48.6,89.75) 48.3,90.05 47.8,90.05 47.7,90.15 47.66,90.15 ; U3.23 91.48,76.6 90.77,75.88 C1.2 ; U33.P22 v1(134.56,18.62) ; v2(132.64,23.84) 132.65,23.84 U33.R14 ; U12.3 42.05,65.1 41.8,65.35 v1(41.7,65.35) ; U33.R22 v1(133.28,18.62) ; v2(133.91,23.84) 133.91,23.84 U33.P14 ; U33.T18 v1(131.24,21.94) ; U33.T14 v1(131.24,24.48) ; U33.T20 v1(131.24,20.67) ; U33.T22 v1(131.2,19.4) ; v2(132.64,28.93) 132.65,28.93 U33.R8 ; v1(48.6,92.25) 48.3,92.55 47.8,92.55 47.7,92.65 47.66,92.65 ; U33.P18 133.91,21.3 v2(133.91,21.3) ; U33.P2 v1(134.56,32.88) ; U33.R12 132.65,26.39 v2(132.64,26.39) ; U33.T12 v1(131.24,25.75) ; v2(133.91,27.66) 133.91,27.66 U33.P10 ; v1(41.8,89.35) 42.05,89.1 U17.3 ; U33.P20 133.91,20.03 v2(133.91,20.03) ; U12.31 42.05,79.1 41.8,79.35 v1(41.7,79.35) ; U33.T16 v1(131.24,23.21) ; U33.P4 133.91,31.47 v2(133.91,31.47) ; U12.30 42.05,78.6 41.8,78.35 v1(41.7,78.35) ; v2(132.64,21.3) 132.65,21.3 U33.R18 ; R18.2 R8.2 v1(49,75.65) ; v2(132.64,31.47) 132.65,31.47 U33.R4 ; U33.P8 133.91,28.93 v2(133.91,28.93) ; U17.2 42.05,88.6 v1(41.8,88.35) ; U17.30 42.15,102.6 41.9,102.35 v1(41.8,102.35) ; R14.2 R6.2 v1(49,81.25) ; v2(133.91,22.57) 133.91,22.57 U33.P16 ; U33.R10 132.65,27.66 v2(132.64,27.66) ; U33.R16 132.65,22.57 v2(132.64,22.57) ; 47.66,68.65 47.7,68.65 47.8,68.55 48.3,68.55 v1(48.6,68.25) ; v1(49,105.25) R78.2 R72.2 ; 118.03,77.62 118.03,78.66 C13.2 ; U33.T2 v1(131.24,32.1) ; U33.R20 132.65,20.03 v2(132.64,20.03)
  TOP w0.3: C9.2 127.63,74.53 127.64,74.53 U11.5 ; U5.8 131.26,74.55 131.24,74.53 C4.1
  TOP w0.5: U14.3 119.27,72.25 C12.2 v1(119.27,69.69) ; R195.2 v1(62.3,35.25) R191.2 ; C185.2 v1(126.3,31.35) ; C185.2 v1(127.58,32.63) ; C185.2 v1(125.02,32.63) ; v1(128.1,27.05) 126.8,27.05 126.2,27.65 ; R249.2 v1(79.9,112.85) R245.2 ; U27.5 v1(64.97,122.45) 64.97,121.55 C70.2 ; C13.2 v1(118.37,79.28) ; C138.2 82.57,33.25 v1(82.57,34.15) U48.5 ; C182.2 102.74,137.66 C181.2 101.61,137.51 v1(101.58,137.53) U59.24 ; R126.2 v1(62.3,128.85) R130.2 ; 24.26,10.35 v1(24.26,11.31) ; 126.2,28.55 126.8,29.15 v1(128.1,29.15) ; 126.2,28.55 126.2,28.65 125.7,29.15 v1(124.3,29.15) ; 126.2,28.55 C84.2 ; 126.2,27.65 126.2,27.55 125.7,27.05 v1(124.3,27.05) ; 126.2,27.65 C84.2 ; R178.2 v1(62.3,67.35) R174.2 ; C128.2 82.57,65.35 v1(82.57,66.25) U45.5 ; 44.67,6.25 v1(44.67,5.45) 44.67,4.55 44.76,4.45 ; R246.2 v1(79.9,134.25) R250.2 ; v1(38.6,132.95) 38.6,133.85 38.98,134.23 C47.2 ; U10.1 v1(80.09,81.95) 79.8,81.66 79.8,81.12 C5.2 ; v1(59.7,84.65) 60.6,84.65 60.98,84.27 C46.2 ; C10.2 C11.2 v1(125.8,82.55) ; C10.2 122.6,83.48 U15.4 ; C10.2 v1(124.3,82.55) ; C49.2 109.18,60.97 108.8,61.35 v1(107.9,61.35) ; C49.2 v1(107.9,60.45) ; C49.2 109.18,59.93 108.8,59.55 v1(107.9,59.55) ; C115.2 64.97,49.35 v1(64.97,50.25) U41.5 ; v1(40.4,132.95) 40.4,133.85 40.02,134.23 C47.2 ; R39.2 v1(62.3,139.55) R35.2 ; v1(133.53,79.78) C3.2 134.54,79.75 U4.8 ; C76.2 136.53,11.61 v1(136.5,11.65) 136.16,12 U30.5 ; 40.97,11.85 R98.2 v1(42,11.85) R94.2 43.03,11.85 ; v1(107.9,87.45) 108.8,87.45 109.18,87.83 C50.2 ; C101.2 64.97,60.05 v1(64.97,60.95) 64.97,61.75 ; 24.26,20.75 v1(24.26,21.71) ; R173.2 v1(62.3,45.95) R177.2 ; 44.67,17.75 v1(44.67,16.95) 44.67,16.05 44.76,15.95 ; C82.2 v1(152.8,21.45) ; R264.2 v1(79.9,123.55) R268.2 ; C184.2 102.74,43.95 C183.2 101.61,43.81 v1(101.58,43.84) U60.24 ; R23.2 v1(77,85.45) ; v1(40.4,34.55) 40.4,33.65 40.02,33.27 C48.2 ; R95.2 v1(42,23.35) R99.2 ; v1(59.7,82.85) 60.6,82.85 60.98,83.23 C46.2 ; C48.2 v1(39.5,34.55) ; C48.2 38.98,33.27 38.6,33.65 v1(38.6,34.55) ; U55.5 v1(82.57,95.75) 82.57,94.85 C171.2 ; R210.2 v1(79.9,72.65) R214.2 ; U1.5 131.81,11.95 v1(132.2,11.55) 132.24,11.52 C75.2 ; C83.2 v1(132.9,37.25) ; C83.2 v1(134.05,35.9) ; C83.2 v1(134.05,38.6) ; U13.5 81.19,89.22 C8.2 v1(78.64,89.22) ; C58.2 64.97,132.25 v1(64.97,133.15) U7.5 ; v1(144.47,77.72) C7.2 143.46,77.75 U8.8 ; C114.2 64.97,27.95 v1(64.97,28.85) U40.5 ; U44.5 v1(82.57,44.85) 82.57,43.95 C121.2 ; C84.2 v1(128.08,28.13) ; C84.2 v1(124.3,28.13) ; C50.2 109.18,88.87 108.8,89.25 v1(107.9,89.25) ; C50.2 v1(107.9,88.35) ; R125.2 v1(62.3,107.45) R129.2 ; C67.2 64.97,100.15 v1(64.97,101.05) U26.5 ; R231.2 v1(79.9,40.55) R227.2 ; R133.2 v1(142.66,10.79) ; U49.5 v1(82.57,55.55) 82.57,54.65 C134.2 ; R192.2 v1(62.3,56.65) R196.2 ; C25.2 v1(115.4,81.95) ; U24.5 v1(64.97,111.75) 64.97,110.85 C57.2 ; R213.2 v1(79.9,51.25) R209.2 ; C46.2 v1(59.7,83.75) ; U6.8 92.7,85.41 C6.2 v1(90.17,85.41) ; C47.2 v1(39.5,132.95) ; C4.1 v1(131.24,72.78) ; C1.2 v1(90.77,74.91) ; U22.5 22.53,27.09 v1(22.53,27.09) C44.2 ; C170.2 82.57,116.25 v1(82.57,117.15) U56.5 ; R112.2 v1(62.3,118.15) R110.2 ; C45.2 v1(22.53,16.69) 22.53,16.69 U23.5 ; 64.97,40.34 v1(64.97,39.55) 64.97,38.65 C99.2 ; C157.2 82.57,105.55 v1(82.57,106.45) U52.5 ; R29.2 v1(104.33,85.81) ; R228.2 v1(79.9,61.95) R232.2 ; C156.2 82.57,126.95 v1(82.57,127.85) U2.5 ; C9.2 v1(127.63,72.78) ; R267.2 v1(79.9,102.15) R263.2 ; C24.2 v1(106.06,79.09) ; 126.06,88.15 v1(127,88.15) ; C2.2 v1(100.03,77.12)
  BOTTOM w0.2: R53.2 R34.1 ; R59.2 R43.1 ; R44.1 R60.2 ; R55.2 R38.1 ; R48.1 R64.2 ; R57.2 R41.1 ; R46.1 R62.2 ; R65.2 R49.1 ; R32.1 R51.2 ; R33.1 R52.2 ; R61.2 R45.1 ; R42.1 R58.2 ; R36.1 R54.2 ; R63.2 R47.1 ; R50.1 R66.2 ; R40.1 R56.2
  BOTTOM w0.3: v1(41.7,78.35) 41.57,78.48 C21.2 ; C28.2 41.67,96.22 v1(41.8,96.35) ; R54.2 v1(7.6,113.84) ; C15.2 41.57,72.22 v1(41.7,72.35) ; C31.2 41.67,88.48 v1(41.8,88.35) ; R43.1 v1(7.6,82.34) ; v1(41.8,103.35) 41.67,103.22 C26.2 ; R58.2 v1(7.6,84.84) ; v1(41.7,64.35) 41.57,64.48 C17.2 ; R52.2 v1(7.6,128.84) ; v1(41.8,95.35) 41.67,95.48 C29.2 ; R45.1 v1(7.6,67.84) ; R64.2 v1(7.6,41.34) ; v1(41.7,65.35) 41.57,65.22 C14.2 ; C27.2 41.67,102.48 v1(41.8,102.35) ; v1(41.8,89.35) 41.67,89.22 C30.2 ; R62.2 v1(7.6,55.84) ; v1(41.7,71.35) 41.57,71.48 C20.2 ; R51.2 v1(7.6,139.34) ; R38.1 v1(7.6,111.34) ; R34.1 v1(7.6,126.34) ; C16.2 41.57,79.22 v1(41.7,79.35) ; R60.2 v1(7.6,70.34) ; R56.2 v1(7.6,99.34) ; R49.1 v1(7.6,38.84) ; R41.1 v1(7.6,96.84) ; R66.2 v1(7.6,26.84) ; R47.1 v1(7.6,53.34)
  BOTTOM w0.5: R223.2 v1(75.56,40.81) ; R210.2 v1(79.9,72.65) ; R125.2 v1(62.3,107.45) ; R259.2 v1(75.56,102.41) ; R263.2 v1(79.9,102.15) ; C177.2 v1(9.7,97.84) ; C108.2 59.63,27.95 v1(59.63,28.85) U42.5 ; R187.2 v1(57.97,35.51) ; R246.2 v1(79.9,134.25) ; U46.5 v1(77.23,44.85) 77.23,43.95 C124.2 ; R227.2 v1(79.9,40.55) ; R238.2 v1(75.56,113.11) ; R189.2 v1(57.97,56.91) ; C64.2 59.63,121.55 v1(59.63,122.45) U29.5 ; U54.5 v1(77.23,127.85) 77.23,126.95 C151.2 ; U51.5 v1(77.23,55.55) 77.23,54.65 C136.2 ; C179.2 v1(9.7,39.34) ; R245.2 v1(79.9,112.85) ; C152.2 77.23,105.55 v1(77.23,106.45) U53.5 ; R174.2 v1(62.3,67.35) ; R27.2 v1(57.97,139.81) ; C123.2 77.23,65.35 v1(77.23,66.25) U47.5 ; R192.2 v1(62.3,56.65) ; U43.5 v1(59.63,50.25) 59.63,49.35 C109.2 ; R108.2 v1(57.97,118.41) ; R264.2 v1(79.9,123.55) ; C143.2 77.23,33.25 v1(77.23,34.15) U50.5 ; 59.63,61.75 v1(59.63,60.95) 59.63,60.05 C96.2 ; C55.2 59.63,132.25 v1(59.63,133.15) U9.5 ; U58.5 v1(77.23,117.15) 77.23,116.25 C164.2 ; R209.2 v1(79.9,51.25) ; C176.2 v1(9.7,127.34) ; R191.2 v1(62.3,35.25) ; R126.2 v1(62.3,128.85) ; R173.2 v1(62.3,45.95) ; C54.2 59.63,110.85 v1(59.63,111.75) U25.5 ; C166.2 77.23,94.85 v1(77.23,95.75) U57.5 ; 39.33,6.25 v1(39.33,5.45) 39.33,4.55 39.24,4.45 ; R228.2 v1(79.9,61.95) ; 59.63,40.34 v1(59.63,39.55) 59.63,38.65 C95.2 ; R171.2 v1(57.97,67.61) ; U28.5 v1(59.63,101.05) 59.63,100.15 C63.2 ; 37.66,22.65 v1(37.66,23.61) ; R35.2 v1(62.3,139.55) ; 39.24,15.95 39.33,16.05 v1(39.33,16.95) 39.33,17.75 ; R225.2 v1(75.56,62.21) ; R123.2 v1(57.97,129.11) ; R207.2 v1(75.56,72.91) ; C178.2 v1(9.7,68.84) ; R202.2 v1(75.56,51.51) ; v1(37.66,12.11) 37.66,11.15 ; R121.2 v1(57.97,107.71) ; R243.2 v1(75.56,134.51) ; R110.2 v1(62.3,118.15) ; R166.2 v1(57.97,46.21) ; R261.2 v1(75.56,123.81) ; C186.2 v1(133.5,63.55)
3V3_MP: length 52.8
  TOP w0.3: U31.5 v1(144.44,12.59)
  TOP w0.5: C91.2 v1(162.78,96.33) ; C91.2 162.35,94.45 ; C91.2 163.25,94.45 ; C91.2 v1(162.78,92.55) ; 162.35,94.45 161.75,95.05 v1(161.75,96.35) ; 162.35,94.45 162.25,94.45 161.75,93.95 v1(161.75,92.55) ; R156.2 R158.2 v1(139.6,105.85) ; U34.8 v1(144.3,112.55) 144.34,112.52 C85.2 ; R154.2 v1(140.53,109.61) ; R146.2 R147.2 v1(137.8,109.35) ; v1(163.85,92.55) 163.85,93.95 163.35,94.45 163.25,94.45 ; v1(163.85,96.35) 163.85,95.05 163.25,94.45 ; U32.16 v1(132.93,115.12) 132.97,115.16 C77.2 ; R140.2 R141.2 v1(118.4,107.75) ; v1(154.7,106.05) R150.2 R149.2 ; v1(118.4,104.95) C87.2 R142.2 ; R160.2 C88.2 v1(154.7,108.85) ; R314.2 v1(154.16,111.58) ; R309.2 R139.2 v1(118.4,110.55) ; R143.2 R145.2 v1(137.8,106.55) ; 144.44,11.55 v1(144.44,12.59) ; v1(155.1,113.95) R316.2 R148.2 ; C89.2 v1(162.56,98.62) ; C90.2 143.2,104.45 v1(143.4,104.65) 143.5,104.75 U35.8 ; R138.2 R311.2 v1(118.4,113.35)
  BOTTOM w0.15: R132.1 150.23,95.17 v1(150.8,95.75)
  BOTTOM w0.5: R153.1 v1(14.37,4.79) ; v1(10.37,4.31) 7.7,4.31 ; R151.1 v1(13.53,143.62)
3V3_OK: length 9.1
  TOP w0.15: 138.71,13.35 139.61,12.45 140.27,12.45 140.94,11.79 140.94,11.75 ; 138.71,13.35 139.7,14.34 139.7,15.45 140.47,16.22 U33.J23 ; 138.71,13.35 U30.2
12V: length 37.1
  TOP w0.15: U33.A13 v1(146.77,25.12) ; U33.A11 v1(146.77,26.39) ; U33.E12 144.09,25.15 v2(144.1,25.15) ; v2(144.1,26.45) 144.1,26.41 U33.C12 ; U33.B1 v1(145.55,33.47) ; U33.C10 v1(144.76,27.8) ; U33.E14 v1(143.5,23.7) ; U33.F1 v1(143.01,33.47) ; U33.A9 v1(146.77,27.66) ; U33.A5 v1(146.77,30.2) ; U33.C14 v1(144.76,23.7) ; U33.E10 v1(143.5,27.8) ; U33.D1 v1(144.28,33.47) ; U33.A3 v1(146.77,31.47) ; U33.A7 v1(146.77,28.93)
  TOP w0.5: 162.78,89.23 163.5,89.95 v1(164.6,89.95) ; 162.78,89.23 C78.2 ; 162.78,89.23 v1(162.78,90.83) ; 163.25,88.95 v1(164.6,88.95) ; 163.25,88.95 163.85,89.55 v1(163.85,90.85) ; 163.25,88.95 C78.2 ; C79.2 v1(145.1,37.75) ; C79.2 143.95,37.1 144.3,36.75 v1(145.1,36.75) ; C79.2 143.95,38.4 144.3,38.75 v1(145.1,38.75) ; C78.2 162.35,88.95 161.75,89.55 v1(161.75,90.85) ; C78.2 162.78,88.47 163.3,87.95 v1(164.6,87.95) ; C80.2 150.35,31 150,31.35 v1(150,32.15) ; C80.2 v1(151,32.15) ; C80.2 151.65,31 152,31.35 v1(152,32.15) ; 140.94,14.55 v1(140.94,15.52)
  BOTTOM w0.5: R131.1 v1(151.37,90.38)
GND: length 425.6
  TOP w0.15: U33.N12 v1(135.68,25.75) ; U33.L2 v1(139,32.88) ; U12.11 v1(41.85,69.1) ; U33.N16 v1(135.68,23.21) ; U17.22 v1(41.85,98.6) ; U33.L22 v1(139,18.62) ; U33.D23 v1(144.28,17.99) ; U33.N2 v1(136.46,32.88) ; U17.32 42.55,103.6 v1(41.9,104.25) ; v1(41.8,70.45) 41.8,70.65 42.25,71.1 U12.15 ; U12.27 43.17,77.07 42.18,77.07 v1(41.8,77.45) 41.8,77.65 42.25,78.1 U12.29 ; U33.L6 v2(138.36,30.2) ; U33.G1 v1(141.74,33.47) ; U33.L20 v2(138.36,20.03) ; U33.L8 v2(138.36,28.93) ; U33.H17 v1(141.36,21.8) ; U33.L4 v2(138.36,31.47) ; U17.15 42.35,95.1 41.9,94.65 v1(41.9,94.45) ; U33.N20 v1(135.68,20.67) ; U33.N6 v1(135.68,29.56) ; U33.L10 v2(138.36,27.66) ; U17.29 42.35,102.1 41.9,101.65 v1(41.9,101.45) 42.25,101.1 U17.27 ; v1(41.9,97.25) 41.9,97.05 42.35,96.6 U17.18 ; U33.M8 v2(137.09,28.93) ; U33.H15 v1(142.14,23.85) ; U33.N4 v1(135.68,30.83) ; U33.N18 v1(135.68,21.94) ; U16.6 v1(112.62,83.33) ; v1(41.8,73.25) 42.45,72.6 U12.18 ; U33.L16 v2(138.36,22.57) ; v1(41.8,63.45) 42.1,63.75 42.1,63.95 42.25,64.1 U12.1 ; U33.H9 v1(142.14,27.66) ; U17.11 v1(41.85,93.1) ; U33.N22 v1(136.46,18.62) ; v2(140.74,28.3) 140.73,28.3 U33.K9 ; v1(41.9,87.45) 42.55,88.1 U17.1 ; U17.4 42.35,89.6 41.9,90.05 v1(41.9,90.25) 42.28,90.63 43.17,90.63 U17.6 ; v2(140.74,27.03) 140.73,27.03 U33.K11 ; v2(140.74,24.46) 140.74,24.47 U33.K13 ; U33.G23 v1(141.74,17.99) ; U16.8 v1(112.62,84.62) ; U33.L18 v2(138.36,21.3) ; U16.10 v1(108.78,83.97) ; U33.K7 v1(140.09,29.7) ; U33.M10 v2(137.09,27.66) ; U33.H11 v1(142.14,26.39) ; U33.M20 v2(137.09,20.03) ; v1(41.8,80.25) 42.45,79.6 U12.32 ; U33.K15 140.74,23.2 v2(140.74,23.19) ; U33.H13 v1(142.14,25.12) ; U33.K17 v1(140.09,21.8) ; U33.M18 v2(137.09,21.3) ; U33.M16 v2(137.09,22.57) ; U33.N10 v1(135.68,27.02) ; U12.22 v1(41.85,74.6) ; U33.A19 v1(146.77,21.31) ; U33.M12 v2(137.09,26.39) ; U33.L14 v2(138.36,23.84) ; U33.M14 v2(137.09,23.84) ; U33.J1 v1(140.47,33.47) ; U33.H7 v1(141.36,29.7) ; U33.N14 v1(135.68,24.48) ; U33.M6 v2(137.09,30.2) ; U33.M22 v1(137.73,18.62) ; U12.6 43.17,66.63 42.18,66.63 v1(41.8,66.25) 41.81,66.25 42.46,65.6 U12.4 ; U33.L12 v2(138.36,26.39) ; U33.N8 v1(135.68,28.29) ; U33.M2 v1(137.73,32.88) ; U5.4 v1(133.05,76.6) ; U33.M4 v2(137.09,31.47)
  TOP w0.3: U30.3 v1(138.65,15.09) ; U3.9 v1(99.35,78.5) ; U11.3 v1(129.36,77.21) ; U31.3 v1(146.16,15.11) ; U5.6 U5.5 v1(131.26,77.21) ; U34.4 v1(148.8,115.22)
  TOP w0.5: v1(79.9,126.85) C156.1 ; R144.1 v1(152.8,20.05) ; U14.9 v1(125.65,76.53) ; v1(128.1,22.6) 126.8,22.6 126.2,22 ; U1.3 v1(134.4,15.16) ; C83.1 v1(136.95,38.6) ; C83.1 v1(138.1,37.25) ; C83.1 v1(136.95,35.9) ; C48.1 v1(39.5,28.95) ; C48.1 38.98,30.23 38.6,29.85 v1(38.6,28.95) ; C48.1 40.02,30.23 40.4,29.85 v1(40.4,28.95) ; C84.1 v1(124.3,21.57) ; C84.1 126.2,21.1 ; C84.1 126.2,22 ; C84.1 v1(128.08,21.57) ; U60.1 v1(92.28,43.84) ; SW2.D v1(30.48,145.73) ; v1(113.5,59.55) 112.6,59.55 112.22,59.93 C49.1 ; v1(87.86,85.09) 87.5,85.44 U13.1 ; v1(155.2,90.85) 155.2,89.55 155.8,88.95 ; v1(65.3,82.85) 64.4,82.85 64.02,83.23 C46.1 ; U48.1 v1(78.39,38.76) ; v1(157.3,90.85) 157.3,89.55 156.7,88.95 ; 155.8,94.45 155.2,95.05 v1(155.2,96.35) ; 155.8,94.45 C91.1 ; 155.8,94.45 155.7,94.45 155.2,93.95 v1(155.2,92.55) ; C75.1 v1(133.97,11.52) ; C7.1 v1(144.47,75.98) ; U4.5 v1(137.5,83.56) ; 43.03,4.45 C40.1 v1(42,4.45) ; 155.8,88.95 155.7,88.95 155.2,88.45 v1(155.2,87.05) ; 155.8,88.95 C78.1 ; R1.1 v1(102.7,74.75) ; v1(62.3,121.45) C70.1 ; C80.1 150.35,27.9 150,27.55 v1(150,26.75) ; C80.1 151.65,27.9 152,27.55 v1(152,26.75) ; C80.1 v1(151,26.75) ; U59.1 v1(92.28,137.53) ; C47.1 40.02,137.27 40.4,137.65 v1(40.4,138.55) ; C47.1 v1(39.5,138.55) ; C47.1 38.98,137.27 38.6,137.65 v1(38.6,138.55) ; C77.1 v1(131.24,115.11) ; DS4.2 v1(152.7,99.95) ; 121.06,104.95 121.73,104.95 v1(122.1,105.32) 122.19,105.41 U32.8 ; v1(79.9,65.25) C128.1 ; C81.1 v1(152.8,25.25) ; C78.1 156.7,88.95 ; C78.1 v1(156.22,87.05) ; C78.1 v1(156.22,90.83) ; 156.7,88.95 156.8,88.95 157.3,88.45 v1(157.3,87.05) ; U40.1 v1(60.8,33.45) ; v1(113.5,89.25) 112.6,89.25 112.22,88.87 C50.1 ; C9.1 v1(129.37,72.81) ; C11.1 v1(125.8,86.15) ; v1(98.47,134.08) 98.83,133.72 U59.21 ; C79.1 140.85,37.1 140.5,36.75 v1(139.7,36.75) ; C79.1 140.85,38.4 140.5,38.75 v1(139.7,38.75) ; C79.1 v1(139.7,37.75) ; v1(62.3,132.15) C58.1 ; 24.26,17.65 v1(24.26,16.68) ; C91.1 v1(156.22,92.55) ; C91.1 v1(156.22,96.33) ; C91.1 156.7,94.45 ; v1(101.64,42.09) C183.1 102.74,41.95 C184.1 ; U7.1 v1(60.8,137.75) ; v1(62.3,100.05) C67.1 ; DS2.2 v1(152.7,88.95) ; C89.1 v1(160.84,98.62) ; U37.1 v1(60.8,65.56) ; U6.5 v1(93.81,89.25) ; C50.1 112.22,87.83 112.6,87.45 v1(113.5,87.45) ; C50.1 v1(113.5,88.35) ; v1(98.47,40.38) 98.83,40.02 U60.21 ; U26.1 v1(60.8,105.66) ; v1(113.5,61.35) 112.6,61.35 112.22,60.97 C49.1 ; 156.7,94.45 157.3,95.05 v1(157.3,96.35) ; 156.7,94.45 156.8,94.45 157.3,93.95 v1(157.3,92.55) ; v1(42,15.95) C42.1 ; v1(101.64,135.78) C181.1 102.74,135.64 C182.1 ; U18.1 v1(40.5,10.05) ; 126.3,35.27 v1(126.3,36.55) ; 126.3,35.27 v1(127.58,35.27) ; 126.3,35.27 v1(125.02,35.27) ; U41.1 v1(60.8,54.86) ; U8.4 v1(137.5,73.94) ; U19.1 v1(40.5,21.55) ; C13.1 117.27,81.02 v1(116.4,80.15) 116.3,80.15 115.44,79.28 C25.1 ; v1(79.9,105.45) C157.1 ; U56.1 v1(78.39,121.75) ; 81.23,78.15 v1(80.11,78.15) 79.8,78.45 79.8,78.98 79.6,79.19 ; v1(62.3,49.25) C115.1 ; v1(128.1,20.5) 126.8,20.5 126.2,21.1 ; 126.2,21.1 126.2,21 125.7,20.5 v1(124.3,20.5) ; C24.1 v1(104.33,79.09) ; v1(65.3,84.65) 64.4,84.65 64.02,84.27 C46.1 ; v1(79.9,43.85) C121.1 ; C90.1 v1(139.6,104.45) ; v1(79.9,33.15) C138.1 ; v1(62.3,27.85) C114.1 ; C3.1 v1(133.53,81.52) ; C180.1 v1(146.16,12.52) ; R137.1 v1(152.8,23.85) ; v1(79.9,54.55) C134.1 ; 126.2,22 126.2,22.1 125.7,22.6 v1(124.3,22.6) ; C76.1 v1(138.26,11.61) ; 91.1,83.69 v1(90.14,83.69) ; 77.23,70.85 v1(78.39,70.85) ; C12.1 v1(117.53,69.69) ; R2.1 v1(101.77,80.91) ; C1.1 v1(89.03,74.91) ; C2.1 v1(102.7,76.15) ; v1(62.3,59.95) C101.1 ; U22.1 v1(26.81,22.45) ; U35.4 v1(151.09,108.56) 151.39,108.85 C88.1 ; v1(62.3,110.75) C57.1 ; U52.1 v1(78.39,111.06) ; U14.10 v1(124.38,76.53) ; C10.1 v1(124.3,86.15) ; v1(79.9,116.15) C170.1 ; U24.1 v1(60.8,116.36) ; 77.23,100.35 v1(78.39,100.35) ; U15.2 v1(117.06,89.59) ; 123.1,72.28 v1(123.1,71.16) ; 27.87,12.05 v1(26.81,12.05) ; C49.1 v1(113.5,60.45) ; C46.1 v1(65.3,83.75) ; SW2.B v1(32.28,145.73) ; DS3.2 v1(152.7,94.45) ; 140.94,13.15 v1(140,13.15) ; U49.1 v1(78.39,60.16) ; v1(79.9,94.75) C171.1 ; C8.1 v1(78.64,87.48) ; U44.1 v1(78.39,49.45) ; v1(62.3,38.55) C99.1 ; U27.1 v1(60.8,127.06) ; 146.06,111.55 v1(146.06,112.52) ; U36.1 v1(60.8,44.16) ; U2.1 v1(78.39,132.45) ; 24.26,28.05 v1(24.26,27.09) ; C4.2 v1(132.97,72.78)
  BOTTOM w0.15: R9.1 R19.1 v1(49,77.05) ; v1(49,79.85) R15.1 R7.1 ; R79.1 R73.1 v1(49,103.85) ; v1(48.6,66.64) 48.31,66.35 47.87,66.35 47.66,66.15 ; R81.1 R77.1 v1(49,101.05) ; v1(48.6,93.14) 48.31,92.85 47.87,92.85 47.66,92.65 ; v1(48.6,69.14) 48.31,68.85 47.87,68.85 47.66,68.65 ; v1(49,78.94) 48.71,78.65 48.26,78.65 R17.1 ; 47.66,90.15 47.87,90.35 48.31,90.35 v1(48.6,90.64) ; v1(49,102.94) 48.71,102.65 48.26,102.65 R75.1
  BOTTOM w0.3: v1(41.9,94.45) 41.37,94.45 41.2,94.62 C29.1 ; v1(41.8,73.25) 41.27,73.25 41.1,73.08 C15.1 ; v1(41.9,104.25) 41.37,104.25 41.2,104.08 C26.1 ; C30.1 41.2,90.08 41.37,90.25 v1(41.9,90.25) ; C21.1 41.1,77.62 41.27,77.45 v1(41.8,77.45) ; v1(41.9,97.25) 41.4,97.25 41.23,97.08 C28.1 ; C16.1 41.1,80.08 41.27,80.25 v1(41.8,80.25) ; v1(41.8,66.25) 41.3,66.25 41.13,66.08 C14.1 ; C20.1 41.13,70.62 41.3,70.45 v1(41.8,70.45) ; v1(41.9,87.45) 41.37,87.45 41.2,87.62 C31.1 ; v1(41.8,63.45) 41.27,63.45 41.1,63.62 C17.1 ; C27.1 41.2,101.62 41.37,101.45 v1(41.9,101.45)
  BOTTOM w0.5: U50.1 v1(81.41,38.76) ; U42.1 v1(63.81,33.45) ; C125.1 v1(73.97,68.95) C127.1 ; C63.1 v1(62.3,100.05) ; C109.1 v1(62.3,49.25) ; R122.1 v1(57.97,99.78) ; U58.1 v1(81.41,121.75) ; U29.1 v1(63.81,127.06) ; C61.1 v1(66,107.45) ; C66.1 v1(56.36,125.15) C69.1 ; C112.1 v1(56.36,31.55) C110.1 ; C123.1 v1(79.9,65.25) ; C178.1 v1(13.3,68.84) ; C122.1 v1(73.97,47.55) C126.1 ; U21.1 v1(43.5,21.55) ; U9.1 v1(63.81,137.75) ; R272.1 v1(98.47,40.38) ; v1(155.1,112.55) R315.1 R317.1 ; C98.1 v1(56.36,42.25) C94.1 ; R318.1 v1(155.1,115.35) ; C148.1 v1(83.6,134.25) ; C151.1 v1(79.9,126.85) ; v1(83.6,61.95) C142.1 ; C55.1 v1(62.3,132.15) ; U51.1 v1(81.41,60.16) ; 82.57,70.85 v1(81.41,70.85) ; v1(42,4.45) C41.1 40.97,4.45 ; C165.1 v1(73.97,98.45) C168.1 ; 37.66,16.65 v1(37.66,15.68) ; C164.1 v1(79.9,116.15) ; C92.1 v1(66,45.95) ; R159.1 R157.1 v1(139.6,107.25) ; C163.1 v1(83.6,102.15) ; R167.1 v1(57.97,38.28) ; C19.1 v1(56.36,135.85) C18.1 ; C95.1 v1(62.3,38.55) ; C124.1 v1(79.9,43.85) ; R310.1 v1(118.4,111.95) ; U28.1 v1(63.81,105.66) ; C120.1 v1(83.6,72.65) ; C65.1 v1(56.36,103.75) C68.1 ; C33.1 v1(36.06,19.65) C35.1 ; C176.1 v1(13.3,127.34) ; C137.1 v1(73.97,36.85) C140.1 ; v1(83.6,40.55) C135.1 ; C54.1 v1(62.3,110.75) ; C177.1 v1(13.3,97.84) ; 82.57,100.35 v1(81.41,100.35) ; R270.1 v1(161.84,86.48) ; C162.1 v1(83.6,123.55) ; C56.1 v1(56.36,114.45) C53.1 ; U25.1 v1(63.81,116.36) ; 37.66,5.15 v1(37.66,4.19) ; C155.1 v1(73.97,130.55) C153.1 ; R190.1 v1(57.97,48.98) ; C111.1 v1(56.36,52.95) C113.1 ; C179.1 v1(13.3,39.34) ; C186.1 v1(133.5,59.95) ; C96.1 v1(62.3,59.95) ; R271.1 v1(98.47,134.08) ; C64.1 v1(62.3,121.45) ; C139.1 v1(73.97,58.25) C141.1 ; C152.1 v1(79.9,105.45) ; C86.1 v1(10.37,2.59) ; R155.1 v1(139.6,108.65) ; R244.1 v1(75.56,126.58) ; U53.1 v1(81.41,111.06) ; R109.1 v1(57.97,110.48) ; R28.1 v1(57.97,131.88) ; R172.1 v1(57.97,59.69) ; C169.1 v1(73.97,119.85) C167.1 ; v1(118.4,114.75) R313.1 R312.1 ; C166.1 v1(79.9,94.75) ; U39.1 v1(63.81,65.56) ; C136.1 v1(79.9,54.55) ; U46.1 v1(81.41,49.45) ; R124.1 v1(57.97,121.19) ; R224.1 v1(75.56,32.88) ; U54.1 v1(81.41,132.45) ; R208.1 v1(75.56,64.98) ; R262.1 v1(75.56,115.89) ; U38.1 v1(63.81,44.16) ; C93.1 v1(66,67.35) ; C52.1 v1(66,139.55) ; C150.1 v1(73.97,109.15) C154.1 ; C107.1 v1(66,56.65) ; C43.1 v1(42,15.95) ; C108.1 v1(62.3,27.85) ; U43.1 v1(63.81,54.86) ; R226.1 v1(75.56,54.28) ; C149.1 v1(83.6,112.85) ; C100.1 v1(56.36,63.65) C97.1 ; R188.1 v1(57.97,27.59) ; R239.1 v1(75.56,105.19) ; C51.1 v1(66,118.15) ; U20.1 v1(43.5,10.05) ; R260.1 v1(75.56,94.48) ; C62.1 v1(66,128.85) ; C106.1 v1(66,35.25) ; R203.1 v1(75.56,43.59) ; C32.1 v1(36.06,8.15) C34.1 ; C143.1 v1(79.9,33.15) ; v1(83.6,51.25) C129.1
